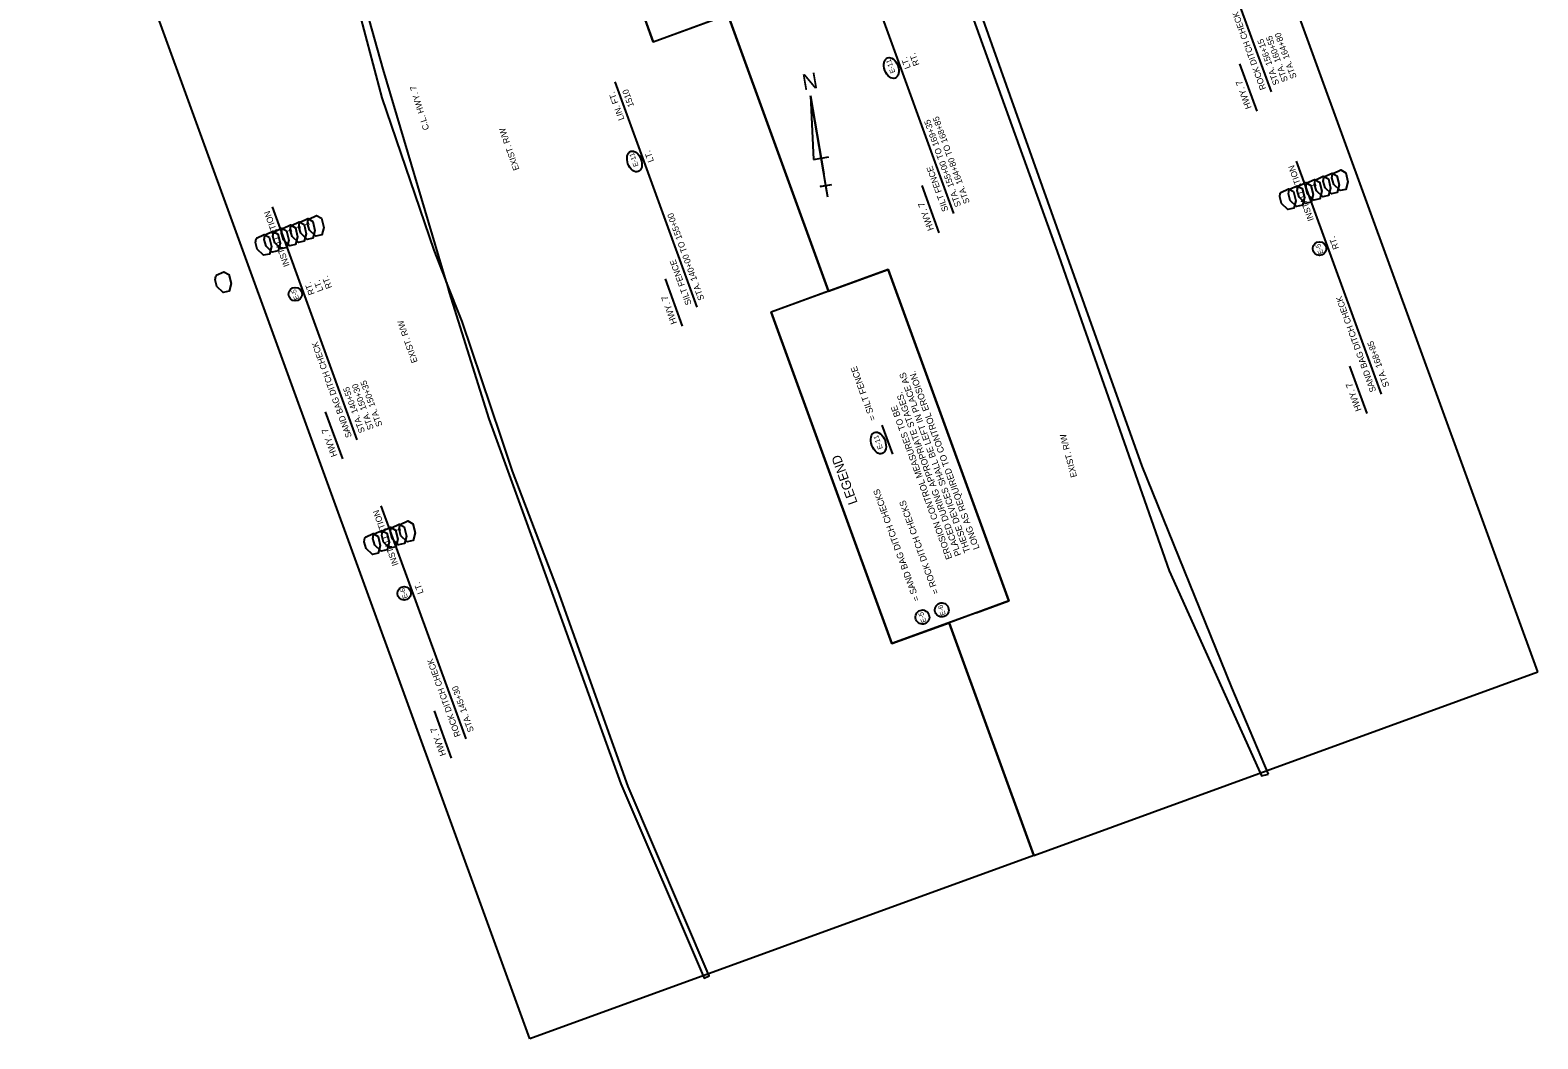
# Model space of a CAD drawing. Extents: x 986289 to 987754, y 1871116 to 1873096.
# Drawn here: x 986289 to 987754, y 1871116 to 1872096 of the extents above; entities that cross this region are included whole.
import ezdxf

# ---------------------------------------------------------------- set-up
doc = ezdxf.new("R2010")
doc.units = 0
for name, color, linetype in [('1', 7, 'Continuous'), ('44', 7, 'Continuous'), ('63', 7, 'Continuous'), ('Default', 7, 'Continuous'), ('Level 1', 7, 'Continuous'), ('Level 44', 7, 'Continuous'), ('NO PLOT', 7, 'Continuous'), ('R_Draft', 7, 'Continuous'), ('S_TREE', 7, 'Continuous')]:
    doc.layers.add(name, color=color, linetype=linetype)

msp = doc.modelspace()

# ---------------------------------------------------------------- linework, layer by layer
at = {"layer": '1'}
for p, q in [((987064.5, 1871841.9), (986966.6, 1872110.8)), ((987122.5, 1871863), (987008.8, 1871821.6)), ((987125.9, 1871499.6), (987008.8, 1871821.6)), ((987207.8, 1871529.4), (987125.9, 1871499.6)), ((987263.9, 1871293.8), (987181.7, 1871519.9))]:
    msp.add_line(p, q, dxfattribs=at)
msp.add_lwpolyline([(987207.8, 1871529.4), (987239.7, 1871541), (987122.5, 1871863)], dxfattribs=at)
for centre in [(987541.5, 1871883.4), (986546.3, 1871839.1), (986652.1, 1871548.4)]:
    msp.add_circle(centre, 6.61, dxfattribs=at)
for centre in [(987125.5, 1872058.8), (986875.9, 1871968)]:
    msp.add_ellipse(centre, major_axis=(-3.6, 9.89), ratio=0.638788, dxfattribs=at)
at = {"layer": '44'}
for p, q in [((987494.9, 1872035.6), (987412.5, 1872262.1)), ((987186.2, 1871917.4), (987106.6, 1872136.2)), ((987480.8, 1872017), (987464.1, 1872062.9)), ((986936.7, 1871826.6), (986857, 1872045.4)), ((987601.8, 1871742), (987519.3, 1871968.4)), ((987172.1, 1871898.8), (987155.4, 1871944.7)), ((986606.5, 1871697.6), (986524.1, 1871924.1)), ((986922.6, 1871808), (986905.9, 1871853.9)), ((987587.7, 1871723.3), (987571, 1871769.2)), ((986592.5, 1871679), (986575.8, 1871724.9)), ((986712.3, 1871407), (986629.9, 1871633.5)), ((986698.2, 1871388.4), (986681.5, 1871434.3))]:
    msp.add_line(p, q, dxfattribs=at)
at = {"layer": '63'}
for p, q in [((987063.8, 1871933.2), (987046.9, 1872031.7)), ((987046.9, 1872031.7), (987059.9, 1871955.9)), ((987046.9, 1872031.7), (987049.7, 1871969.8)), ((987049.7, 1871969.8), (987064.9, 1871972.4)), ((987063.8, 1871933.2), (987059.9, 1871955.9)), ((987056.2, 1871943.6), (987067.6, 1871945.5)), ((987061.9, 1871944.5), (987056.2, 1871943.6)), ((987063.8, 1871933.2), (987061.9, 1871944.5))]:
    msp.add_line(p, q, dxfattribs=at)
at = {"layer": 'Default'}
for q in [(986748.9, 1872483.8), (987030, 1872133.9)]:
    msp.add_line((986894.2, 1872084.4), q, dxfattribs=at)
at = {"layer": 'Level 1'}
for centre, major_axis, ratio in [((987112.9, 1871694.5), (-3.7, 10.3), 0.622952), ((987174.5, 1871532.3), (2.35, -6.47), 0.97521), ((987155.7, 1871525.4), (2.35, -6.47), 0.97521)]:
    msp.add_ellipse(centre, major_axis=major_axis, ratio=ratio, dxfattribs=at)
at = {"layer": 'Level 44'}
msp.add_lwpolyline([(987126.8, 1871683.5), (987116.5, 1871711.8)], dxfattribs=at)
at = {"layer": 'NO PLOT'}
for points in [[(987753.7, 1871472.1), (987208, 1872971.2), (986718.3, 1872793), (986821.2, 1872510.2), (986884.7, 1872533.2), (987030, 1872133.9), (986966.6, 1872110.8), (987064.5, 1871841.9), (987122.5, 1871863), (987239.7, 1871541), (987181.7, 1871519.9), (987263.9, 1871293.8)], [(987753.7, 1871472.1), (987208, 1872971.2), (986718.3, 1872793), (986821.2, 1872510.2), (986884.7, 1872533.2), (987030, 1872133.9), (986966.6, 1872110.8), (987064.5, 1871841.9), (987122.5, 1871863), (987239.7, 1871541), (987181.7, 1871519.9), (987263.9, 1871293.8)], [(987753.7, 1871472.1), (987208, 1872971.2), (986718.3, 1872793), (986821.2, 1872510.2), (986884.7, 1872533.2), (987030, 1872133.9), (986966.6, 1872110.8), (987064.5, 1871841.9), (987122.5, 1871863), (987239.7, 1871541), (987181.7, 1871519.9), (987263.9, 1871293.8)], [(987491.8, 1871372.7), (987456.2, 1871457.1), (987369.2, 1871671.9), (987295.1, 1871880), (987205.8, 1872130.8), (987121, 1872363), (986947.4, 1872834.5), (986933.7, 1872873.1), (986927.1, 1872871.4), (986945.7, 1872820.2), (986924.6, 1872802.1), (986920.3, 1872785.6), (986930.5, 1872752.2), (986941.1, 1872766.8), (986957.6, 1872786.8), (987010.9, 1872635.9), (987123.9, 1872331.6), (987288.2, 1871875.9), (987395.4, 1871570.4), (987485.3, 1871371)], [(986774.2, 1871115.6), (986369.2, 1872228.3), (986415.6, 1872245.1), (986348.7, 1872429.1), (986362.4, 1872434.1), (986288.7, 1872636.6), (986718.3, 1872793), (986821.2, 1872510.2), (986748.9, 1872483.8), (986894.2, 1872084.4), (986966.6, 1872110.8), (987064.5, 1871841.9), (987008.8, 1871821.6), (987125.9, 1871499.6), (987181.7, 1871519.9), (987263.9, 1871293.8)], [(986774.2, 1871115.6), (986369.2, 1872228.3), (986415.6, 1872245.1), (986348.7, 1872429.1), (986362.4, 1872434.1), (986288.7, 1872636.6), (986718.3, 1872793), (986821.2, 1872510.2), (986748.9, 1872483.8), (986894.2, 1872084.4), (986966.6, 1872110.8), (987064.5, 1871841.9), (987008.8, 1871821.6), (987125.9, 1871499.6), (987181.7, 1871519.9), (987263.9, 1871293.8)], [(986774.2, 1871115.6), (986369.2, 1872228.3), (986415.6, 1872245.1), (986348.7, 1872429.1), (986362.4, 1872434.1), (986288.7, 1872636.6), (986718.3, 1872793), (986821.2, 1872510.2), (986748.9, 1872483.8), (986894.2, 1872084.4), (986966.6, 1872110.8), (987064.5, 1871841.9), (987008.8, 1871821.6), (987125.9, 1871499.6), (987181.7, 1871519.9), (987263.9, 1871293.8)]]:
    msp.add_lwpolyline(points, close=True, dxfattribs=at)
msp.add_lwpolyline([(986566.3, 1872272.3), (986630.5, 1872029.9), (986681, 1871882), (986692, 1871853.6), (986693, 1871850.9), (986693, 1871850.9), (986693.2, 1871850.3), (986695.9, 1871840.7), (986734.3, 1871718.1), (986785.4, 1871577.2), (986862.7, 1871363.5), (986943.5, 1871174.5), (986948.5, 1871176.8), (986869.9, 1871360.7), (986801.7, 1871550.9), (986757.5, 1871667.2), (986746.1, 1871701.2), (986708.4, 1871812.4), (986693.1, 1871850.8), (986693, 1871851), (986692.8, 1871851.7), (986631.8, 1872057.7), (986585.5, 1872222.9)], dxfattribs=at)
at = {"layer": 'S_TREE'}
for points in [[(987520.8, 1871944.1), (987528.3, 1871947.6), (987533.1, 1871944.8), (987535.3, 1871936), (987533.4, 1871928.6), (987527.7, 1871927.3), (987521.6, 1871933.2), (987519.7, 1871939.7), (987520.3, 1871943.3), (987521.5, 1871944.6)], [(987520.8, 1871944.1), (987528.3, 1871947.6), (987533.1, 1871944.8), (987535.3, 1871936), (987533.4, 1871928.6), (987527.7, 1871927.3), (987521.6, 1871933.2), (987519.7, 1871939.7), (987520.3, 1871943.3), (987521.5, 1871944.6)], [(987529.3, 1871947.2), (987536.8, 1871950.6), (987541.6, 1871947.9), (987543.8, 1871939.1), (987541.8, 1871931.7), (987536.1, 1871930.4), (987530, 1871936.3), (987528.2, 1871942.8), (987528.8, 1871946.4), (987530, 1871947.6)], [(987537.8, 1871950.2), (987545.2, 1871953.7), (987550.1, 1871951), (987552.2, 1871942.2), (987550.3, 1871934.8), (987544.6, 1871933.5), (987538.5, 1871939.4), (987536.6, 1871945.8), (987537.2, 1871949.5), (987538.4, 1871950.7)], [(987546.2, 1871953.3), (987553.7, 1871956.8), (987558.5, 1871954.1), (987560.7, 1871945.2), (987558.7, 1871937.9), (987553, 1871936.6), (987546.9, 1871942.5), (987545.1, 1871948.9), (987545.7, 1871952.6), (987546.9, 1871953.8)], [(987554.7, 1871956.4), (987562.1, 1871959.9), (987567, 1871957.1), (987569.1, 1871948.3), (987567.2, 1871940.9), (987561.5, 1871939.7), (987555.4, 1871945.5), (987553.6, 1871952), (987554.2, 1871955.6), (987555.4, 1871956.9)], [(987503.9, 1871937.9), (987511.4, 1871941.4), (987516.2, 1871938.7), (987518.4, 1871929.8), (987516.4, 1871922.5), (987510.7, 1871921.2), (987504.7, 1871927.1), (987502.8, 1871933.5), (987503.4, 1871937.2), (987504.6, 1871938.4)], [(987503.9, 1871937.9), (987511.4, 1871941.4), (987516.2, 1871938.7), (987518.4, 1871929.8), (987516.4, 1871922.5), (987510.7, 1871921.2), (987504.7, 1871927.1), (987502.8, 1871933.5), (987503.4, 1871937.2), (987504.6, 1871938.4)], [(987512.4, 1871941), (987519.9, 1871944.5), (987524.7, 1871941.8), (987526.8, 1871932.9), (987524.9, 1871925.5), (987519.2, 1871924.3), (987513.1, 1871930.2), (987511.3, 1871936.6), (987511.9, 1871940.3), (987513.1, 1871941.5)], [(987512.4, 1871941), (987519.9, 1871944.5), (987524.7, 1871941.8), (987526.8, 1871932.9), (987524.9, 1871925.5), (987519.2, 1871924.3), (987513.1, 1871930.2), (987511.3, 1871936.6), (987511.9, 1871940.3), (987513.1, 1871941.5)], [(986534.1, 1871902.8), (986541.5, 1871906.3), (986546.4, 1871903.6), (986548.5, 1871894.8), (986546.6, 1871887.4), (986540.9, 1871886.1), (986534.8, 1871892), (986532.9, 1871898.4), (986533.6, 1871902.1), (986534.8, 1871903.3)], [(986542.5, 1871905.9), (986550, 1871909.4), (986554.8, 1871906.7), (986557, 1871897.8), (986555, 1871890.5), (986549.3, 1871889.2), (986543.3, 1871895.1), (986541.4, 1871901.5), (986542, 1871905.2), (986543.2, 1871906.4)], [(986551, 1871909), (986558.5, 1871912.5), (986563.3, 1871909.7), (986565.4, 1871900.9), (986563.5, 1871893.5), (986557.8, 1871892.3), (986551.7, 1871898.2), (986549.9, 1871904.6), (986550.5, 1871908.3), (986551.7, 1871909.5)], [(986559.4, 1871912.1), (986566.9, 1871915.6), (986571.7, 1871912.8), (986573.9, 1871904), (986572, 1871896.6), (986566.3, 1871895.3), (986560.2, 1871901.2), (986558.3, 1871907.7), (986558.9, 1871911.3), (986560.1, 1871912.6)], [(986508.7, 1871893.6), (986516.2, 1871897.1), (986521, 1871894.4), (986523.2, 1871885.5), (986521.2, 1871878.1), (986515.5, 1871876.9), (986509.4, 1871882.8), (986507.6, 1871889.2), (986508.2, 1871892.9), (986509.4, 1871894.1)], [(986517.2, 1871896.7), (986524.6, 1871900.2), (986529.5, 1871897.4), (986531.6, 1871888.6), (986529.7, 1871881.2), (986524, 1871880), (986517.9, 1871885.8), (986516, 1871892.3), (986516.6, 1871895.9), (986517.8, 1871897.2)], [(986525.6, 1871899.8), (986533.1, 1871903.2), (986537.9, 1871900.5), (986540.1, 1871891.7), (986538.1, 1871884.3), (986532.4, 1871883), (986526.3, 1871888.9), (986524.5, 1871895.4), (986525.1, 1871899), (986526.3, 1871900.2)], [(986469.5, 1871857.4), (986477, 1871860.9), (986481.8, 1871858.2), (986484, 1871849.3), (986482, 1871842), (986476.3, 1871840.7), (986470.2, 1871846.6), (986468.4, 1871853), (986469, 1871856.7), (986470.2, 1871857.9)], [(986631.4, 1871609.1), (986638.9, 1871612.6), (986643.7, 1871609.9), (986645.8, 1871601.1), (986643.9, 1871593.7), (986638.2, 1871592.4), (986632.1, 1871598.3), (986630.3, 1871604.7), (986630.9, 1871608.4), (986632.1, 1871609.6)], [(986631.4, 1871609.1), (986638.9, 1871612.6), (986643.7, 1871609.9), (986645.8, 1871601.1), (986643.9, 1871593.7), (986638.2, 1871592.4), (986632.1, 1871598.3), (986630.3, 1871604.7), (986630.9, 1871608.4), (986632.1, 1871609.6)], [(986639.9, 1871612.2), (986647.3, 1871615.7), (986652.2, 1871613), (986654.3, 1871604.1), (986652.4, 1871596.8), (986646.7, 1871595.5), (986640.6, 1871601.4), (986638.7, 1871607.8), (986639.3, 1871611.5), (986640.5, 1871612.7)], [(986648.3, 1871615.3), (986655.8, 1871618.8), (986660.6, 1871616), (986662.8, 1871607.2), (986660.8, 1871599.8), (986655.1, 1871598.6), (986649, 1871604.4), (986647.2, 1871610.9), (986647.8, 1871614.5), (986649, 1871615.8)], [(986614.5, 1871603), (986622, 1871606.5), (986626.8, 1871603.7), (986628.9, 1871594.9), (986627, 1871587.5), (986621.3, 1871586.2), (986615.2, 1871592.1), (986613.4, 1871598.6), (986614, 1871602.2), (986615.2, 1871603.5)], [(986614.5, 1871603), (986622, 1871606.5), (986626.8, 1871603.7), (986628.9, 1871594.9), (986627, 1871587.5), (986621.3, 1871586.2), (986615.2, 1871592.1), (986613.4, 1871598.6), (986614, 1871602.2), (986615.2, 1871603.5)], [(986622.9, 1871606.1), (986630.4, 1871609.5), (986635.2, 1871606.8), (986637.4, 1871598), (986635.5, 1871590.6), (986629.7, 1871589.3), (986623.7, 1871595.2), (986621.8, 1871601.7), (986622.4, 1871605.3), (986623.6, 1871606.5)], [(986622.9, 1871606.1), (986630.4, 1871609.5), (986635.2, 1871606.8), (986637.4, 1871598), (986635.5, 1871590.6), (986629.7, 1871589.3), (986623.7, 1871595.2), (986621.8, 1871601.7), (986622.4, 1871605.3), (986623.6, 1871606.5)]]:
    msp.add_lwpolyline(points, dxfattribs=at)

# ---------------------------------------------------------------- texts
at = {"layer": '1'}
for s, p in [('E-11', (987129.4, 1872054.7)), ('E-11', (986879.9, 1871963.9)), ('E-5 ', (987545.4, 1871878.9)), ('E-5 ', (986550.2, 1871834.6)), ('E-6 ', (986655.8, 1871544.3))]:
    msp.add_text(s, height=4.8, rotation=110, dxfattribs=at).set_placement(p)
at = {"layer": '44'}
for s, height, p in [('ROCK DITCH CHECK', 6, (987489.7, 1872038.8)), ('STA. 156+15', 6, (987502.6, 1872043.5)), ('STA. 160+55', 6, (987511, 1872046.6)), ('STA. 164+80', 6, (987519.5, 1872049.7)), ('LT.', 6, (987144.4, 1872059.2)), ('RT.', 6, (987152.9, 1872062.1)), ('LIN. FT.', 6, (986866.2, 1872009.2)), ('1510', 6, (986875.6, 1872022)), ('HWY. 7', 6.25, (987475.6, 1872020.3)), ('STA. 155+00 TO 169+35', 6, (987193.4, 1871925.1)), ('STA. 164+80 TO 168+85', 6, (987201.8, 1871928.2)), ('LT.', 6, (986894.9, 1871968.4)), ('SILT FENCE      ', 6, (987181, 1871920.6)), ('INSTALLATION', 6, (987536.1, 1871911.4)), ('1', 6, (987538.9, 1871943.8)), ('INSTALLATION', 6, (986540.9, 1871867)), ('HWY. 7', 6.25, (987166.9, 1871902.1)), ('1', 6, (986552.1, 1871902.6)), ('1', 6, (986560.6, 1871905.7)), ('STA. 140+00 TO 155+00', 6, (986943.9, 1871834.3)), ('1', 6, (986543.6, 1871899.5)), ('RT.', 6, (987560.6, 1871883.8)), ('SILT FENCE      ', 6, (986931.5, 1871829.8)), ('RT.', 6, (986565.3, 1871839.5)), ('LT.', 6, (986573.7, 1871842.7)), ('RT.', 6, (986582.2, 1871845.6)), ('HWY. 7', 6.25, (986917.4, 1871811.2)), ('SAND BAG DITCH CHECK', 6, (987596.6, 1871745.2)), ('SAND BAG DITCH CHECK', 6, (986601.4, 1871700.9)), ('STA. 168+85', 6, (987609.5, 1871749.9)), ('STA. 140+55', 6, (986614.2, 1871705.5)), ('STA. 150+30', 6, (986622.7, 1871708.6)), ('STA. 150+35', 6, (986631.1, 1871711.7)), ('HWY. 7', 6.25, (987582.5, 1871726.6)), ('HWY. 7', 6.25, (986587.3, 1871682.3)), ('INSTALLATION', 6, (986646.7, 1871576.4)), ('1', 6, (986649.4, 1871608.9)), ('LT.', 6, (986671.1, 1871549)), ('ROCK DITCH CHECK', 6, (986707.2, 1871410.2)), ('STA. 145+30', 6, (986720, 1871414.9)), ('HWY. 7', 6.25, (986693, 1871391.7))]:
    msp.add_text(s, height=height, rotation=110, dxfattribs=at).set_placement(p)
at = {"layer": '63'}
msp.add_text('N', height=15.4, rotation=9.7144, dxfattribs=at).set_placement((987040.3, 1872037.1))
at = {"layer": 'Level 1'}
for s, height, p in [('= SILT FENCE', 6.25, (987110.6, 1871717.6)), ('THESE DEVICES SHALL BE LEFT IN PLACE AS ', 6.25, (987202.4, 1871589.1)), ('LONG AS REQUIRED TO CONTROL EROSION.', 6.25, (987211.3, 1871592.3)), ('PLACED DURING APPROPRIATE STAGES. ', 6.25, (987193.6, 1871585.9)), ('EROSION CONTROL MEASURES TO BE', 6.25, (987184.8, 1871582.7)), ('E-11 ', 4.88, (987117.3, 1871689.3)), ('= SAND BAG DITCH CHECKS', 6.25, (987153, 1871542)), ('= ROCK DITCH CHECKS', 6.25, (987171.8, 1871548.9)), ('E-5 ', 4.88, (987159.7, 1871520.9)), ('E-6 ', 4.88, (987178.4, 1871527.9))]:
    msp.add_text(s, height=height, rotation=110, dxfattribs=at).set_placement(p)
at = {"layer": 'Level 44'}
msp.add_text('LEGEND', height=9.14, rotation=110, dxfattribs=at).set_placement((987092.8, 1871636.6))
at = {"layer": 'R_Draft'}
for s, rotation, p in [('C.L. HWY. 7', 107.2156, (986676.5, 1871999.5)), ('EXIST. R/W', 109.2927, (986764.1, 1871960.5)), ('EXIST. R/W', 109.2927, (986665.3, 1871773.5)), ('EXIST. R/W', 104.7013, (987305.9, 1871661.9))]:
    msp.add_text(s, height=6, rotation=rotation, dxfattribs=at).set_placement(p)

doc.saveas('drawing.dxf')
